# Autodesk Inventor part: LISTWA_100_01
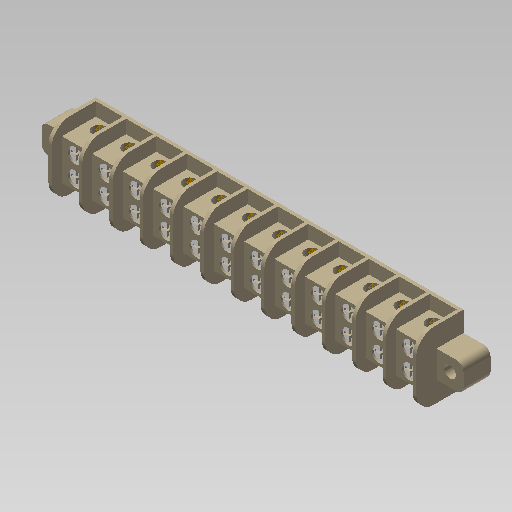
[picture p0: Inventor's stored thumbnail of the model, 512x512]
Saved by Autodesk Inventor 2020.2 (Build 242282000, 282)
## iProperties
Manager: www.cadconsulting.pl
Company: Fabian Stasiak CAD Consulting
GlobalPropertyList: <PropertyList/>
Created: 2014-09
Part Number: LISTWA_100_01
Material: Ogólny
Document SubType Name: Modeling
Designer: F.Stasiak
Density: 1 g/cm^3
Appearance: Beżowa
Categories: <MemberInstance><Categories><Category DisplayName="" Mnemonic="CABLEANDHARNESS" InternalName="e4a7e005-5e42-4d16-b293-125e7f0d0512"><Category DisplayName="" Mne
Catalog Web Link: www.expertbooks.pl
Author: F.Stasiak
Subject: Zbiór ćwiczeń. Autodesk Inventor 2020. Kurs Professional
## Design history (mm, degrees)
sketch "Szkic1"
  geometry: L1 (-4, -6)-(4, -6); L2 (4, -6)-(4, 6); L3 (4, 6)-(-4, 6); L4 (-4, 6)-(-4, -6); L5 (-4, -6)-(4, 6); L6 (4, -6)-(-4, 6); 1 further point
  constraints: 12 end point, 2 midpoint, 2 parallel, 1 horizontal, 1 perpendicular
  dimensions: "d0" = 8 distance of L3.end L2.end; "d1" = 12 distance of L2.end L1.end
extrude "Wyciągnięcie proste1" new body sketch "Szkic1" distance "d2" = 10; taper "d3" = 0 deg
sketch "Szkic2"
  geometry: L1 (0, 0)-(8, 0) reference; L2 (8, 0)-(8, 10) reference; L3 (0, 10)-(8, 10) reference; L4 (0, 0)-(0, 10) reference; C1 r 2 at (4, 3); 2 further points
  constraints: 1 centre point, 1 midpoint, 1 vertical alignment
  dimensions: "d4" = 4 diameter of C1; "d7" = 3 distance from line of C1.centre L1
extrude "Wyciągnięcie proste2" cut sketch "Szkic2" extent not by distance; stored distance "d5" = 10; taper "d6" = 0 deg
sketch "Szkic3"
  geometry: L1 (-4, -6)-(4, -6) reference; L2 (4, -6)-(4, 6) reference; L3 (4, 6)-(-4, 6) reference; L4 (-4, 6)-(-4, -6) reference; L5 (0, -3)-(0, 3); C1 r 2.25 at (0, -3); C2 r 2.25 at (0, 3); 2 further points
  constraints: 2 centre point, 2 end point, 1 coincident, 1 equal radius, 1 midpoint, 1 vertical
  dimensions: "d8" = 4.5 diameter of C1; "d9" = 6 distance of L5.start L5.end
extrude "Wyciągnięcie proste3" cut sketch "Szkic3" distance "d10" = 0.5; taper "d11" = 0 deg
sketch "Szkic4"
  geometry: L1 (0.3, 0.875)-(-0.3, 0.875); L2 (-0.3, 0.875)-(-0.3, -2.625); L3 (-0.3, -2.625)-(0.3, -2.625); L4 (0.3, -2.625)-(0.3, 0.875); L5 (0.3, 0.875)-(-0.3, -2.625); L6 (-0.3, 0.875)-(0.3, -2.625); L7 (1.8, -0.575)-(-1.8, -0.575); L8 (-1.8, -0.575)-(-1.8, -1.175); L9 (-1.8, -1.175)-(1.8, -1.175); L10 (1.8, -1.175)-(1.8, -0.575); L11 (1.8, -0.575)-(-1.8, -1.175); L12 (-1.8, -0.575)-(1.8, -1.175); C1 r 2.25 at (0, -0.875) reference; 4 further points
  constraints: 24 end point, 6 midpoint, 4 parallel, 2 horizontal, 2 perpendicular, 1 coincident
  dimensions: "d14" = 0.6 distance of L3.end L2.end; "d15" = 3.5 distance of L2.end L1.end; "d12" = 3.6 distance of L9.end L8.end; "d13" = 0.6 distance of L8.end L7.end
extrude "Wyciągnięcie proste4" cut sketch "Szkic4" taper "d17" = -5 deg; distance "d18" = 1
mirror "Odbicie lustrzane1"
sketch "Szkic5"
  geometry: L1 (0, 12)-(0, 0) reference; L2 (0, 0)-(10, 0) reference; L3 (10, 12)-(10, 0) reference; L4 (0, 12)-(10, 12) reference; L5 (0, 16)-(13, 16); L6 (13, 16)-(13, -4); L7 (13, -4)-(0, -4); L8 (0, -4)-(0, 16); 2 further points
  constraints: 8 end point, 2 midpoint, 2 parallel, 1 horizontal, 1 perpendicular
  dimensions: "d19" = 20 distance of L7.end L5.start; "d20" = 13 distance of L6.end L7.end
extrude "Wyciągnięcie proste5" join sketch "Szkic5" distance "d21" = 1; taper "d22" = 0 deg
chamfer "Faza1" distance "d23" = 3.25; stored, may be unused: second distance "d24" = 2, angle "d25" = 45 deg
fillet "Zaokrąglenie1" dims "d26" = 4
sketch "Szkic6"
  geometry: L1 (5, 10)-(5, -10) reference; L2 (4, -6)-(-4, -6) reference; L3 (4, -6)-(4, -10) reference; L4 (4, -10)-(5, -10) reference; L5 (5, 10)-(5, -10) reference; L6 (4, 10)-(5, 10) reference; L7 (4, 10)-(4, 6) reference; L8 (-4, 6)-(4, 6) reference; L9 (-4, -6)-(-4, 6) reference; L10 (5, -10)-(-4, -10); L11 (-4, -10)-(-4, 10); L12 (-4, 10)-(5, 10); L13 (5, 10)-(5, -10); 1 further point
  constraints: 8 end point, 2 parallel, 1 horizontal, 1 perpendicular
extrude "Wyciągnięcie proste6" join sketch "Szkic6" distance "d27" = 1; taper "d28" = 0 deg
pattern_linear "Szyk prostokątny1" dims "d31" = 9
sketch "Szkic7"
  geometry: L1 (-8.093, 20)-(1, 20); L2 (1, 0)-(1, 20); L3 (-8.093, 0)-(1, 0); L4 (-11.828, 2.078)-(-10.922, 1.172); L5 (-13, 4.907)-(-13, 15.093); L6 (-10.922, 18.828)-(-11.828, 17.922); A1 r 4 centre (-8.093, 16) between (-8.093, 20) and (-10.922, 18.828); A2 r 4 centre (-8.093, 4) between (-10.922, 1.172) and (-8.093, 0); A3 r 4 centre (-9, 4.907) between (-13, 4.907) and (-11.828, 2.078); A4 r 4 centre (-9, 15.093) between (-11.828, 17.922) and (-13, 15.093); 1 further point
  constraints: 12 end point, 8 point on circle, 4 centre point
extrude "Wyciągnięcie proste7" join sketch "Szkic7" distance "d32" = 1; taper "d33" = 0 deg
sketch "Szkic8"
  geometry: L1 (-1, -4)-(-1, 16) reference; L2 (-1, 10)-(7, 10); L3 (7, 10)-(7, 2); L4 (7, 2)-(-1, 2); L5 (-1, 2)-(-1, 10); 2 further points
  constraints: 8 end point, 2 midpoint, 2 parallel, 1 horizontal, 1 perpendicular
  dimensions: "d34" = 8 distance of L3.end L4.end; "d35" = 8 distance of L2.end L3.end
extrude "Wyciągnięcie proste8" join sketch "Szkic8" distance "d36" = 8; taper "d37" = 0 deg
fillet "Zaokrąglenie2" dims "d38" = 2
sketch "Szkic9"
  geometry: L1 (-8, 4)-(-8, 8) reference; L2 (-2, 2)-(-6, 2) reference; C1 r 1.75 at (-4, 6); 3 further points
  constraints: 2 midpoint, 1 centre point, 1 horizontal alignment, 1 vertical alignment
  dimensions: "d39" = 3.5 diameter of C1
extrude "Wyciągnięcie proste9" cut sketch "Szkic9" extent not by distance; stored distance "d40" = 8; taper "d41" = 0 deg
node "Płaszczyzna konstrukcyjna1"
mirror "Odbicie lustrzane2"
sketch "Szkic41"
  geometry: C1 r 2 at (4, 3) reference
node "101"
sketch "Szkic42"
  geometry: C1 r 2 at (4, 3) reference
node "102"
sketch "Szkic43"
  geometry: C1 r 2 at (4, 3) reference
node "103"
sketch "Szkic44"
  geometry: C1 r 2 at (4, 3) reference
node "104"
sketch "Szkic45"
  geometry: C1 r 2 at (4, 3) reference
node "105"
sketch "Szkic46"
  geometry: C1 r 2 at (4, 3) reference
node "106"
sketch "Szkic47"
  geometry: C1 r 2 at (4, 3) reference
node "107"
sketch "Szkic48"
  geometry: C1 r 2 at (4, 3) reference
node "108"
sketch "Szkic49"
  geometry: C1 r 2 at (4, 3) reference
node "109"
sketch "Szkic50"
  geometry: C1 r 2 at (4, 3) reference
node "110"
sketch "Szkic51"
  geometry: C1 r 2 at (4, 3) reference
node "111"
sketch "Szkic52"
  geometry: C1 r 2 at (4, 3) reference
node "112"
sketch "Szkic53"
  geometry: C1 r 2 at (4, 7) reference
node "201"
sketch "Szkic54"
  geometry: C1 r 2 at (4, -3) reference
node "202"
sketch "Szkic55"
  geometry: C1 r 2 at (4, -3) reference
node "203"
sketch "Szkic56"
  geometry: C1 r 2 at (4, -3) reference
node "204"
sketch "Szkic57"
  geometry: C1 r 2 at (4, -3) reference
node "205"
sketch "Szkic58"
  geometry: C1 r 2 at (4, -3) reference
node "206"
sketch "Szkic59"
  geometry: C1 r 2 at (4, -3) reference
node "207"
sketch "Szkic60"
  geometry: C1 r 2 at (4, -3) reference
node "208"
sketch "Szkic61"
  geometry: C1 r 2 at (4, -3) reference
node "209"
sketch "Szkic62"
  geometry: C1 r 2 at (4, -3) reference
node "210"
sketch "Szkic63"
  geometry: C1 r 2 at (4, -3) reference
node "211"
sketch "Szkic64"
  geometry: C1 r 2 at (4, 7) reference
node "212"
node "Bryła1"
node "Pętla rzutowana1"
node "Pętla rzutowana2"
node "Pętla rzutowana3"
node "Pętla rzutowana4"
node "Pętla rzutowana5"
